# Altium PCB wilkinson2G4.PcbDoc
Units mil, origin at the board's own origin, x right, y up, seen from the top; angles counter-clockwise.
Board outline 3937.01 x 1377.95 mil, 2 copper layers (Top Layer, Bottom Layer); 17 components, 6 nets, 39 pads, 6 vias.
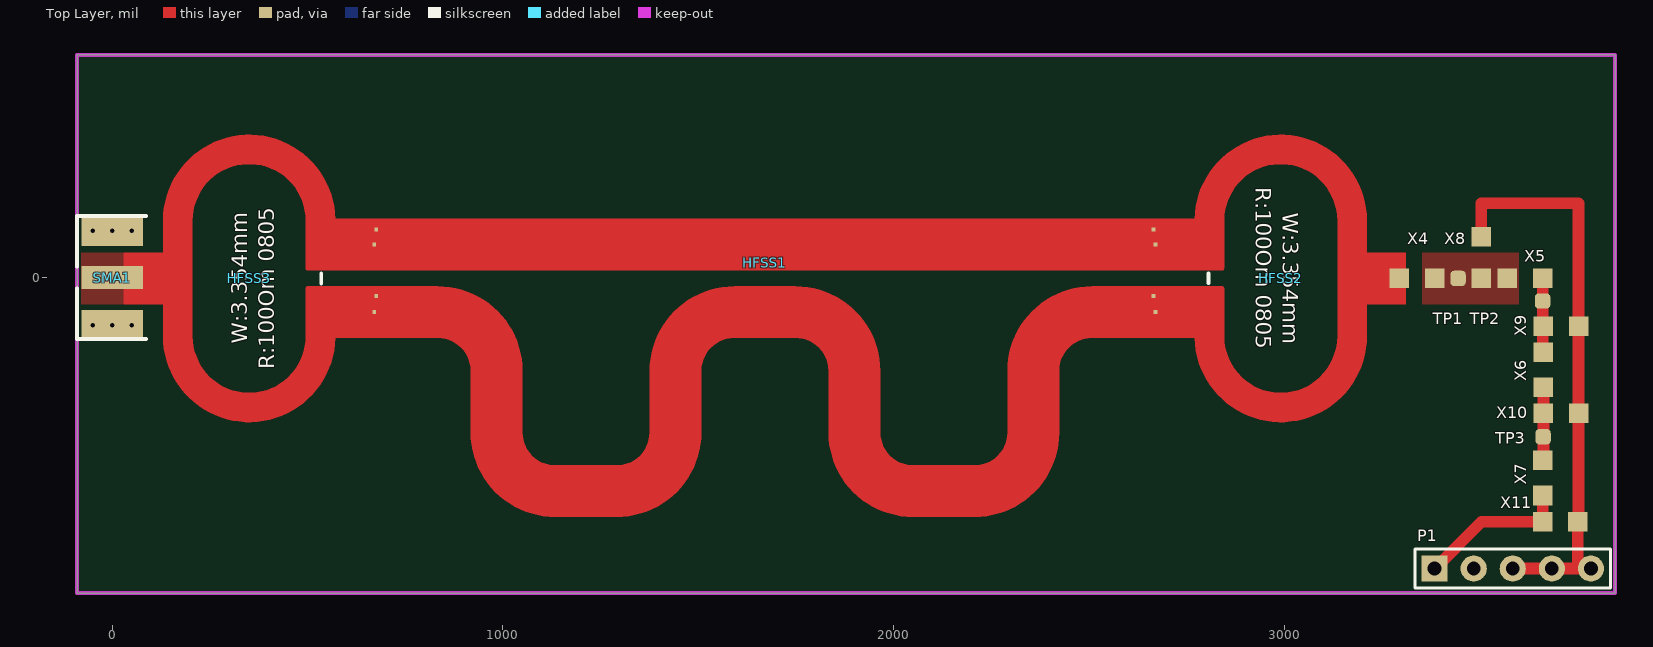
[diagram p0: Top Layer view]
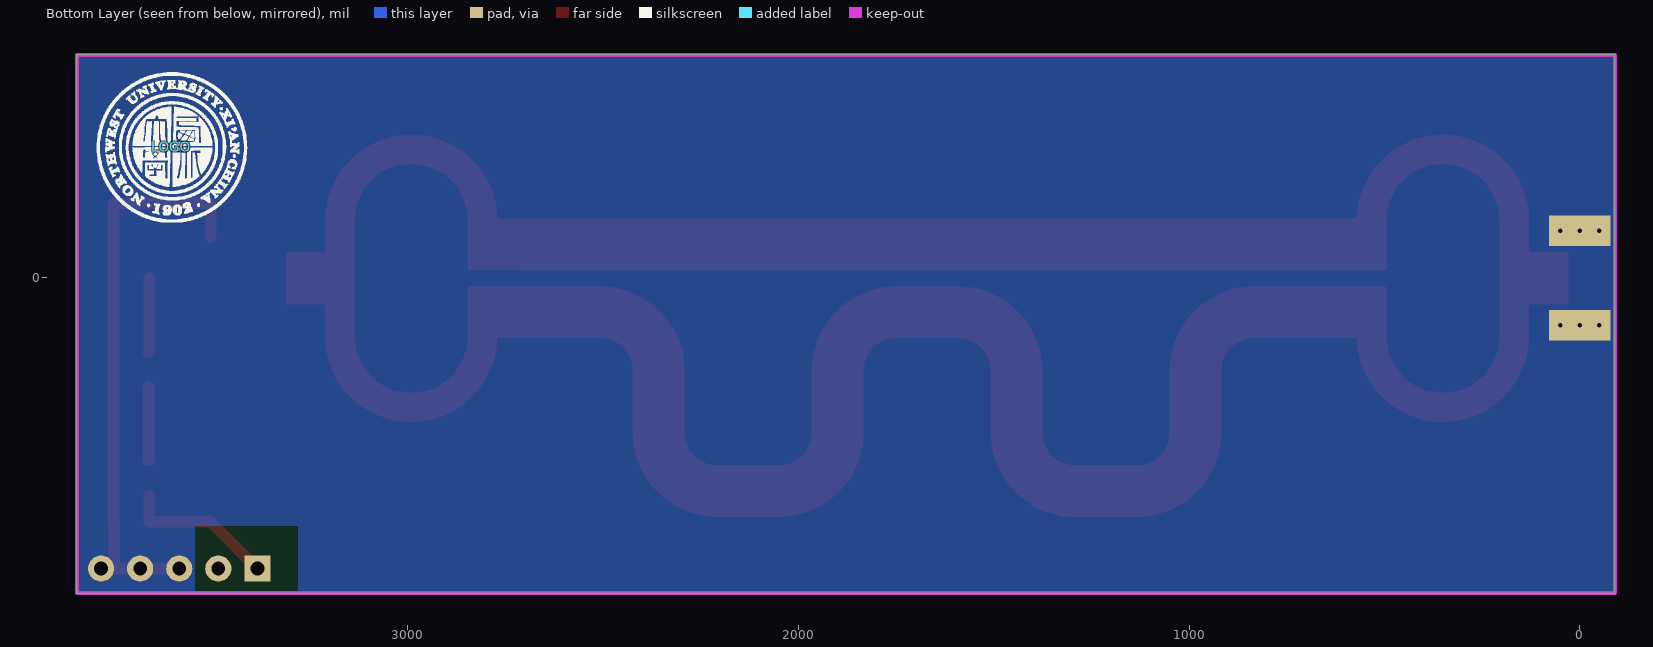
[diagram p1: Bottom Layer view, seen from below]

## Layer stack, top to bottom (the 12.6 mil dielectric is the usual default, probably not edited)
Top Solder: solder mask 0.4, Solder Resist, Dk 3.5
Top Layer: signal copper 1.4
Dielectric 1: dielectric 12.6, FR-4, Dk 4.8
Bottom Layer: signal copper 1.4
Bottom Solder: solder mask 0.4, Solder Resist, Dk 3.5

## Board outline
-90,-807.95 -90,570 3847.01,570 3847.01,-807.95

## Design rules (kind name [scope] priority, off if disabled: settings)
Clearance [All] p1: gap=0 ignorepadtopadclearanceinfootprint=TRUE
HoleToHoleClearance [All] p1: gap=5 allowstackedmicrovias=TRUE
MinimumSolderMaskSliver [All] p1: minsoldermaskwidth=5
PlaneClearance [All] p1: clearance=0
PlaneConnect [All] p1: planeconnectstyle=Direct reliefexpansion=20 reliefentries=4 reliefconductorwidth=10 reliefairgap=10
PolygonConnect [All] p1: connectstyle=Direct reliefconductorwidth=10 reliefentries=4 polygonreliefangle="90 Angle" airgapwidth=10
RoutingVias [All] p1: holewidth=28 width=50 viastyle="Through Hole" minholewidth=28 minwidth=50 maxholewidth=28 maxwidth=50
SilkToSilkClearance [All] p1: silktosilkclearance=5
SilkToSolderMaskClearance [IsPad] p1: minsilkscreentomaskgap=0 clearancetoexposedcopper=TRUE
SolderMaskExpansion [All] p1: expansion=4 istentingtop=FALSE
Width [All] p1: maxlimit=5000 minlimit=5 preferedwidth=10
24 further rules are at their usual default settings.

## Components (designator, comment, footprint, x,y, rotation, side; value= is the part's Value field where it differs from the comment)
HFSS1 "DELAYPI2G4BD2FR4" DELAYPI2G4BD2FR4 675.76,18.22 r0 top locked
HFSS2 "WILKINSON2G4BD2FR4" WILKINSON2G4BD2FR4 2991.51,-4.39 r180 top locked
HFSS3 "WILKINSON2G4BD2FR4" WILKINSON2G4BD2FR4 350,0 r0 top locked
LOGO "NWULOGO" NorthwestLogo 3605,335 r180 bottom
P1 "ZEADER-1*5P" HDR2.54-LI-5P 3585,-745 r0 top locked
SMA1 "SMA" SMA-FR2 0,0 r90 top locked
TP1 "TEST" HFSS#1 3445,0 r90 top locked
TP2 "TEST" HFSS#2 3660,-60 r90 top locked
TP3 "TEST" HFSS#3 3662.63,-407.6 r90 top locked
X4 "X" X0805#1 3340,-2.2 r180 top locked
X5 "X" X0805#1 3616.49,-1.61 r0 top locked
X6 "X" X0805#1 3663.5,-236.07 r270 top locked
X7 "X" X0805#1 3662.26,-512.92 r90 top locked
X8 "X" X0805#2 3504.48,42.86 r270 top locked
X9 "X" X0805#1 3708.5,-124.25 r180 top locked
X10 "X" X0805#1 3708.41,-347.8 r180 top locked
X11 "X" X0805#1 3706.49,-624.97 r180 top locked

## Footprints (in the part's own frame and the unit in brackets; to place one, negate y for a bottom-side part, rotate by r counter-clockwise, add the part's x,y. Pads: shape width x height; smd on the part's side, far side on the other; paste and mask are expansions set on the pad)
DELAYPI2G4BD2FR4 [mil]
  rect 10x10 smd: 1(0,105) 2(1990,105) 3(0,-65) 4(1990,-65)
  Top Layer region: 241.99,-414.85 258.43,-497.52 305.25,-567.6 375.33,-614.42 458,-630.87 458,-630.87 616,-630.87 698.67,-614.42 768.75,-567.6 815.57,-497.52 832.01,-414.85 832.01,-414.85 832.01,-256.85 838.41,-224.71 856.61,-197.47 883.86,-179.26 916,-172.87 916,-172.87 1074,-172.87 1106.14,-179.26 1133.39,-197.47 1151.59,-224.71 1157.98,-256.85 1157.99,-256.85 1157.99,-414.85 1174.43,-497.52 1221.25,-567.6 1291.33,-614.42 1374,-630.87 1374,-630.87 1532,-630.87 1614.67,-614.42 1684.75,-567.6 1731.57,-497.52 1748.01,-414.85 1748.01,-414.85 1748.01,-256.85 1754.41,-224.71 1772.61,-197.47 1799.86,-179.26 1832,-172.87 1832,-172.87 1990,-172.87 1990,-40.84 1832,-40.84 1749.33,-57.28 1679.25,-104.11 1632.43,-174.19 1615.98,-256.85 1615.99,-256.85 1615.99,-414.85 1609.59,-446.99 1591.39,-474.24 1564.14,-492.45 1532,-498.84 1532,-498.84 1374,-498.84 1341.86,-492.45 1314.61,-474.24 1296.41,-446.99 1290.01,-414.85 1290.01,-414.85 1290.01,-256.85 1273.57,-174.19 1226.75,-104.11 1156.67,-57.28 1074,-40.84 1074,-40.84 916,-40.84 833.33,-57.28 763.25,-104.11 716.43,-174.19 699.98,-256.85 699.99,-256.85 699.99,-414.85 693.59,-446.99 675.39,-474.24 648.14,-492.45 616,-498.84 616,-498.84 458,-498.84 425.86,-492.45 398.61,-474.24 380.41,-446.99 374.01,-414.85 374.01,-414.85 374.01,-256.85 357.57,-174.19 310.75,-104.11 240.67,-57.28 158,-40.84 158,-40.84 0,-40.84 0,-172.87 158,-172.87 190.14,-179.26 217.39,-197.47 235.59,-224.71 241.99,-256.85 241.99,-256.85
  Top Layer region: 0,0 0,132.03 1990,132.03 1990,0
HDR2.54-LI-5P [mm]
  rect 1.7x1.7 hole 0.9: 1(-5.08,0)
  round 1.7 hole 0.9: 2(-2.54,0) 3(0,0) 4(2.54,0) 5(5.08,0)
  silkscreen extent -6.35,-1.27 6.35,1.27, body extent -6.35,-1.27 6.35,1.27, height 2.54
HFSS#1 [mm]
  rrect50% 1x1 smd: 1(-0.056,0)
HFSS#2 [mm]
  rrect50% 1x1 smd: 1(0,-0.038)
HFSS#3 [mm]
  rrect50% 1x1 smd: 1(0,0)
NorthwestLogo [mil]
  silkscreen extent -191,-194 194,189
SMA-FR2 [mm] "偏脚"
  rect 1.5x4 smd: 1(0,0)
  rect 2x4 smd: 2(-3.099,0) 2(3.048,0)
  rect 2x4 smd far side: 3(-3.099,0) 3(3.048,0)
  silkscreen extent -4,-2.2 4,2.3, body extent -3.25,-1.33 3.25,12.17, height 3.75
WILKINSON2G4BD2FR4 [mil]
  rect 10x10 smd: 1(-320.02,-2.2) 2(320.76,84.24) 3(320.76,-88.63)
  Top Layer region: -320.02,-68.21 -220.02,-68.21 -220.02,-149.63 -220.01,-149.73 -190.86,-259.17 -111.21,-339.68 -2.09,-370 107.68,-342.12 189.11,-263.41 220.7,-154.65 220.7,-154.64 320.76,-154.64 320.76,-22.61 150.69,-22.61 148.77,-23 147.15,-24.08 146.06,-25.71 145.68,-27.63 145.68,-27.63 145.68,-149.63 145.68,-149.73 126.18,-222.34 73,-275.49 0.37,-294.94 -72.25,-275.49 -125.44,-222.34 -144.94,-149.73 -144.94,-149.73 -144.93,-149.63 -144.93,145.24 -144.94,145.34 -125.44,217.95 -72.25,271.09 0.37,290.54 73,271.09 126.18,217.95 145.68,145.34 145.68,145.34 145.68,145.24 145.68,23.24 146.06,21.32 147.15,19.69 148.77,18.6 150.69,18.22 150.69,18.22 320.76,18.22 320.76,150.25 220.7,150.25 189.11,259.02 107.68,337.73 -2.09,365.61 -111.21,335.29 -190.86,254.78 -220.01,145.34 -220.01,145.34 -220.02,145.24 -220.02,63.82 -320.02,63.82
  silkscreen extent 185,-15 185,10
X0805#1 [mil]
  rect 50x50 smd: 1(-45,0) 2(45,0)
  body extent -39,-24 39,24, height 22
X0805#2 [mil]
  rect 50x50 smd: 1(-62.14,0) 2(45,0)
  body extent -39,-24 39,24, height 22

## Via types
v1: diameter 24, hole 12, Top Layer to Bottom Layer, 6 vias

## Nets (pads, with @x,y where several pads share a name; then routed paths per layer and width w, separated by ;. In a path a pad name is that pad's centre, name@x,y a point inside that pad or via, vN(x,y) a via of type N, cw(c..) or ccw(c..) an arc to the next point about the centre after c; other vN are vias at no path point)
GND: P1.3 P1.4 P1.5 SMA1.2 SMA1.3 X8.1 X9.1 X10.1 X11.1 | length 1471
  Top Layer w30: X8.1 3504.48,190 3753.5,190 X9.1 3753.5,-347.8 X10.1 3753.41,-624.97 X11.1 3751.49,-745 ; P1.3 P1.4 3751.49,-745 ; P1.5 3751.49,-745
  other v1: -50,-122 0,-122 50,-122 -50,120 0,120 50,120
NetHFSS1_1: HFSS1.1 HFSS1.2 HFSS1.3 HFSS1.4 HFSS2.1 HFSS2.2 HFSS2.3 HFSS3.1 HFSS3.2 HFSS3.3 SMA1.1 X4.2
NetP1_1: P1.1 X7.1 X11.2 | length 394
  Top Layer w30: P1.1 3505.03,-624.97 X11.2 3661.49,-557.92 X7.1
NetTP1_1: TP1.1 X4.1 X5.1 X8.2
NetTP2_1: TP2.1 X5.2 X6.1 X9.2 | length 191.5
  Top Layer w30: X5.2 3661.49,-191.07 X6.1
NetTP3_1: TP3.1 X6.2 X7.2 X10.2 | length 188.1
  Top Layer w30: X7.2 3663.5,-467.92 X6.2
pads on no net: P1.2

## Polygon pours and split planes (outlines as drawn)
NetHFSS1_1 on Top Layer "CUP" (solid, remove dead copper, pour order 0): 79.99,63.82 -80,63.82 -80,-68.21 79.99,-68.21
NetTP1_1 on Top Layer "CUP" (solid, remove dead copper, pour order 5): 3353.82,63.82 3353.82,-68.21 3600,-68.21 3600,63.82
GND on Bottom Layer "CUP" (solid, remove dead copper, pour order 6): -90,570 -90,-808 3847.01,-808 3847.01,570

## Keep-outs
Keep-Out Layer:
  the board outline again, w10

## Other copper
Top Layer:
  region net NetHFSS1_1: 2720.79,-154.64 2646.51,-154.64 2646.51,-22.61 2720.79,-22.61
  region net NetHFSS1_1: 2720.79,150.25 2646.51,150.25 2646.51,18.22 2720.79,18.22
  region net NetHFSS1_1: 620.73,-154.64 695,-154.64 695,-22.61 620.73,-22.61
  region net NetHFSS1_1: 620.73,150.25 695,150.25 695,18.22 620.73,18.22
Multi-Layer:
  pour cut-out: 3280,-635 3545,-635 3545,-810 3280,-810

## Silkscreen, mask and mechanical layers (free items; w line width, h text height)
Top Solder:
  region: -90,-807.99 -90,570 3847,570 3847,-807.99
